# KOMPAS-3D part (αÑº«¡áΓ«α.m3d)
File: created 29.01.2016 13:47:21, last saved 25.07.2016 11:06:17.
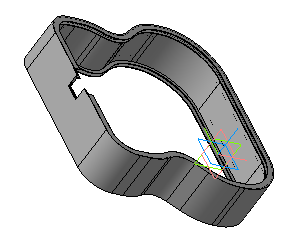
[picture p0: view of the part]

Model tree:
1. Эскиз:1
2. Операция выдавливания:1
     Толщина стенки 1 = 2; Толщина стенки 2 = 8; Расстояние 1 = 1
3. Эскиз:2
4. Операция выдавливания:2
     Толщина стенки 1 = 2; Толщина стенки 2 = 8; Расстояние 1 = 5
5. Эскиз:3
6. Операция выдавливания:3
     Толщина стенки 1 = 2; Толщина стенки 2 = 8; Расстояние 1 = 1
7. Эскиз:4
8. Операция выдавливания:4
     Толщина стенки 1 = 2; Толщина стенки 2 = 2.5; Расстояние 1 = 50
9. Эскиз:5
10. Вырезать элемент выдавливания:1
     Толщина стенки 2 = 1.2; Расстояние 1 = 40
11. Эскиз:6
12. Операция выдавливания:5
     Толщина стенки 1 = 2; Толщина стенки 2 = 2.5; Расстояние 1 = 10
13. Эскиз:7
14. Операция выдавливания:6
     Толщина стенки 1 = 2; Толщина стенки 2 = 8; Расстояние 1 = 1
15. Эскиз:8
16. Операция выдавливания:7
     Толщина стенки 1 = 2; Толщина стенки 2 = 8; Расстояние 1 = 5
17. Эскиз:9
18. Операция выдавливания:8
     Толщина стенки 1 = 2; Толщина стенки 2 = 8; Расстояние 1 = 1
19. Эскиз:10
20. Вырезать элемент выдавливания:2
     Толщина стенки 2 = 1.2; Расстояние 1 = 23
21. Эскиз:11
22. Вырезать элемент выдавливания:3
     Толщина стенки 2 = 1.2; Расстояние 1 = 1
